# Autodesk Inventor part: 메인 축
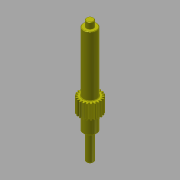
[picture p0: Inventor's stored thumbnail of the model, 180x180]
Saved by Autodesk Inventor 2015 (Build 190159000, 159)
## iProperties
Created: 2016-02
Part Number: 메인 축
Material: 강철, 연강
Document SubType Name: Modeling
Categories: <?xml version="1.0" encoding="UTF-16"?> <MemberInstance><Categories><FamilyTemplate><FamilyTemplateParameter ValueType="xs:double" Id="1" ObjectReferenceKey="da
Density: 7.86 g/cm^3
Mass: 187.503 g
Surface Area: 82.0529 cm^2
Volume: 23.8554 cm^3
Appearance: 노란색
Author: mdu
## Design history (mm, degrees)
sketch "Sketch1"
  geometry: C1 r 12 at (0, 0)
  constraints: 1 centre point
  dimensions: "d0" = 24 diameter of C1 (= da_da)
extrude "Extrusion1" new body sketch "Sketch1" distance "d1" = 20 (= da_b); taper "d2" = 0 deg
workplane "Work Plane2"
feature "피치 지름" dims "d4" = 10, "d5" = 0
workplane "Work Plane8"
workplane "Work Plane9"
chamfer "모따기1" distance "d49" = 1; stored, may be unused: second distance "d50" = 2, angle "d51" = 45 deg
sketch "스케치3"
  geometry: C1 r 7.5 at (0, 0); 1 further point
  constraints: 1 centre point, 1 coincident
  dimensions: "d52" = 15 diameter of C1
extrude "돌출2" join sketch "스케치3" distance "d53" = 66; taper "d54" = 0 deg
sketch "스케치4"
  geometry: C1 r 4 at (0, 0); 1 further point
  constraints: 1 centre point, 1 coincident
  dimensions: "d55" = 8 diameter of C1
extrude "돌출3" join sketch "스케치4" distance "d56" = 7; taper "d57" = 0 deg
sketch "스케치5"
  geometry: C1 r 7.5 at (0, 0) reference; C2 r 7.5 at (0, 0) reference; 1 further point
extrude "돌출4" join sketch "스케치5" distance "d62" = 16; taper "d63" = 0 deg
sketch "스케치6"
  geometry: C1 r 4 at (0, 0); 1 further point
  constraints: 1 centre point, 1 coincident
  dimensions: "d64" = 8 diameter of C1
extrude "돌출5" join sketch "스케치6" distance "d65" = 30; taper "d66" = 0 deg
chamfer "모따기2" distance "d58" = 0.5; stored, may be unused: second distance "d59" = 2, angle "d60" = 45 deg
fillet "모깎기1" dims "d61" = 0.5
feature "스퍼 기어" dims "da_b" = 20, "da_d" = 22, "da_aw" = 31, "da_da" = 24, "da_df" = 19.5, "da_dw" = 22, angle "da_beta" = 0 deg, "da_lefttooth" = 0, "da_righttooth" = 0
sketch "스케치7" dims "d68" = 18
  geometry: C1 r 0.25 at (0, -9); 2 further points
  constraints: 2 vertical alignment, 1 centre point, 1 coincident, 2 other
  dimensions: "d67" = 0.5 diameter of C1
extrude "돌출6" join sketch "스케치7" distance "d69" = 0.3; taper "d70" = 0 deg
feature "면 이동1"
feature "면 이동2"
feature "면 이동3"
body "Solid1"
sketch "Sketch2"
  geometry: C1 r 12 at (0, 0) reference; C2 r 11 at (0, 0)
  constraints: 1 centre point, 1 coincident
  dimensions: "d3" = 22 diameter of C2 (= da_dw)
body "Srf1"
node "투영된 루프1"
other parameters: "d16" = 31 (= da_aw), "d17" = 0, "d34" = 1.428 (computed from da_z), "d39" = 0, "d41" = 0, "d43" = 31 (= da_aw), "d46" = 31 (= da_aw), "d47" = 0, "d48" = 0
